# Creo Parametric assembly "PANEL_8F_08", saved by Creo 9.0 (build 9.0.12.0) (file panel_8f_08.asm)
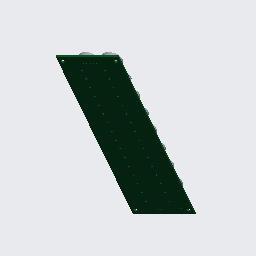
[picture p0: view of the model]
Units: millimeter Newton Second (mmNs); MM, TONNE, SECS

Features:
  1. coordinate system "PANEL_8F_08"
  2. imported feature "Import Feature id 4"
  3. component "PCB_8F"
  4. component "TX_8F_T1"
  5. component "TX_8F_T1"
  6. component "TX_8F_T1"
  7. component "TX_8F_T1"
  8. component "TX_8F_T1"
  9. component "TX_8F_T1"
  10. component "TX_8F_T1"
  11. component "TX_8F_T1"
  12. component "TX_8F_T1"
  13. component "TX_8F_T1"
  14. component "TX_8F_T1"
  15. component "TX_8F_T1"
  16. component "TX_8F_T1"
  17. component "TX_8F_T1"
  18. component "TX_8F_T1"
  19. component "TX_8F_T1"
